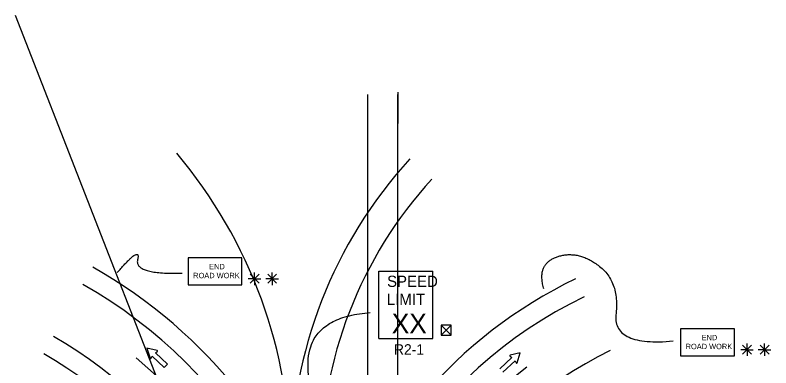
# Model space of a CAD drawing. Extents: x 16604 to 19504, y 6997 to 8305.
# Drawn here: x 16712 to 17319, y 8022 to 8305 of the extents above; entities that cross this region are included whole.
import ezdxf

# ---------------------------------------------------------------- set-up
doc = ezdxf.new("R2010")
doc.units = 0
for name, color, linetype in [('ALI_LEGAL_EX', 7, 'Continuous'), ('MT_SCRATCH_LEVEL_E', 7, 'Continuous'), ('PAVT_EDGE_EX', 7, 'Continuous'), ('TRAFFIC_SIGNS_PR', 7, 'Continuous'), ('TYPICAL_TEXT_DIMEN_PR', 7, 'Continuous')]:
    doc.layers.add(name, color=color, linetype=linetype)

msp = doc.modelspace()

# ---------------------------------------------------------------- linework, layer by layer
at = {"layer": 'ALI_LEGAL_EX'}
for p, q in [((16712.44, 8305.01), (16934.47, 7736.64)), ((16995.53, 8241.3), (16995.53, 7423.16)), ((17019.53, 8241.3), (17019.53, 7423.16))]:
    msp.add_line(p, q, dxfattribs=at)
for points in [[(17019.95, 8218.16), (17019.95, 8243.16)], [(16828.4, 8013.47), (16809.73, 8030.1)], [(17103.8, 8007.23), (17123.26, 8022.93)]]:
    msp.add_lwpolyline(points, dxfattribs=at)
for centre, radius, start, end in [((16545.79, 7943.78), 388, 0, 40.19078), ((17297.79, 7943.78), 364, 137.51601, 180), ((17297.79, 7943.78), 340, 137.51601, 180)]:
    msp.add_arc(centre, radius, start, end, dxfattribs=at)
at = {"layer": 'MT_SCRATCH_LEVEL_E'}
for p, q in [((16826.46, 8035.9), (16818.35, 8037.87)), ((16818.35, 8037.87), (16820.78, 8029.9)), ((16821.6, 8029.78), (16822.6, 8031.29)), ((16822.6, 8031.29), (16832.22, 8022.17)), ((16825.17, 8034.01), (16826.62, 8035.08)), ((16834.8, 8024.89), (16825.17, 8034.01)), ((17111.32, 8030.27), (17101.65, 8021.2)), ((17109.87, 8031.35), (17111.32, 8030.27)), ((17118.14, 8034.12), (17110.04, 8032.16)), ((17115.69, 8026.14), (17118.14, 8034.12)), ((16832.22, 8022.17), (16834.8, 8024.89)), ((17104.21, 8018.47), (17113.88, 8027.53)), ((17113.88, 8027.53), (17114.86, 8026.02))]:
    msp.add_line(p, q, dxfattribs=at)
for centre, start, end in [((16826.34, 8035.45), 306.59404, 76.33096), ((16821.22, 8030.04), 196.98269, 326.52165), ((17110.16, 8031.71), 103.58205, 233.12102), ((17115.25, 8026.29), 213.1934, 342.93033)]:
    msp.add_arc(centre, 0.463, start, end, dxfattribs=at)
at = {"layer": 'PAVT_EDGE_EX'}
for centre, radius, start, end in [((16575.73, 7751.28), 404, 15.917, 60.4732), ((17327.73, 7751.28), 380, 115.76575, 163.04831), ((16575.73, 7751.28), 388, 0, 60.4732), ((17327.73, 7751.28), 364, 115.76575, 180), ((16575.73, 7751.28), 340, 0, 60.4732), ((17327.73, 7751.28), 316, 115.76575, 180), ((16575.73, 7751.28), 324, 0, 60.4732)]:
    msp.add_arc(centre, radius, start, end, dxfattribs=at)
at = {"layer": 'TRAFFIC_SIGNS_PR'}
for p, q in [((17004.62, 8099.47), (17047.82, 8099.47)), ((17004.62, 8045.47), (17004.62, 8099.47)), ((17047.82, 8045.47), (17047.82, 8099.47)), ((17004.62, 8045.47), (17047.82, 8045.47))]:
    msp.add_line(p, q, dxfattribs=at)
for points in [[(16851.38, 8088.59), (16894.58, 8088.59), (16894.58, 8110.19), (16851.38, 8110.19)], [(17246.83, 8031.65), (17290.03, 8031.65), (17290.03, 8053.25), (17246.83, 8053.25)]]:
    msp.add_lwpolyline(points, close=True, dxfattribs=at)
at = {"layer": 'TYPICAL_TEXT_DIMEN_PR'}
for p, q in [((16901.14, 8097.1), (16908.31, 8089.93)), ((16908.31, 8097.1), (16901.14, 8089.93)), ((16904.73, 8093.51), (16904.73, 8098.53)), ((16922.44, 8097.1), (16915.26, 8089.93)), ((16915.27, 8097.1), (16922.44, 8089.93)), ((16918.85, 8093.51), (16918.85, 8098.53)), ((16904.73, 8093.51), (16899.63, 8093.51)), ((16904.73, 8093.51), (16908.31, 8093.51)), ((16904.73, 8093.51), (16909.76, 8093.51)), ((16904.73, 8093.51), (16904.73, 8088.45)), ((16918.85, 8093.51), (16913.75, 8093.51)), ((16918.85, 8093.51), (16922.44, 8093.51)), ((16918.85, 8093.51), (16923.89, 8093.51)), ((16918.85, 8093.51), (16918.85, 8088.45)), ((17054.49, 8056.35), (17062.49, 8048.35)), ((17054.49, 8048.35), (17062.49, 8056.35)), ((17300.17, 8036.57), (17300.17, 8041.58)), ((17314.3, 8036.57), (17314.3, 8041.58)), ((17300.17, 8036.57), (17295.08, 8036.57)), ((17296.59, 8040.15), (17303.76, 8032.98)), ((17303.76, 8040.15), (17296.59, 8032.98)), ((17300.17, 8036.57), (17303.76, 8036.57)), ((17300.17, 8036.57), (17305.21, 8036.57)), ((17300.17, 8036.57), (17300.17, 8031.51)), ((17314.3, 8036.57), (17309.2, 8036.57)), ((17317.89, 8040.15), (17310.71, 8032.98)), ((17310.72, 8040.15), (17317.89, 8032.98)), ((17314.3, 8036.57), (17317.89, 8036.57)), ((17314.3, 8036.57), (17319.34, 8036.57)), ((17314.3, 8036.57), (17314.3, 8031.51))]:
    msp.add_line(p, q, dxfattribs=at)
msp.add_lwpolyline([(17054.49, 8056.35), (17054.49, 8048.35), (17062.49, 8048.35), (17062.49, 8056.35)], close=True, dxfattribs=at)
for points in [[(16794.5, 8098.38), (16813.71, 8120.98), (16807.86, 8096.7), (16846.56, 8098.1)], [(17137.08, 8085.28), (17131.07, 8105.28), (17164, 8116.81), (17197.85, 8091.44), (17192.05, 8039.02), (17240.86, 8043.55)], [(16954.55, 7912.33), (16985.92, 7921.76), (17000.86, 7981.24), (16947.66, 7986.96), (16947.76, 8062.72), (16997.69, 8066.32)]]:
    msp.add_open_spline(points, degree=2, dxfattribs=at)

# ---------------------------------------------------------------- texts
at = {"layer": 'TRAFFIC_SIGNS_PR'}
for s, height, p in [('END', 4.31, (16868.25, 8101.11)), ('ROAD WORK', 4.31, (16855.44, 8093.93)), ('SPEED', 9, (17011.11, 8086.94)), ('LIMIT', 9, (17010.92, 8072.54)), ('XX', 15.785, (17014.87, 8049.7)), ('END', 4.31, (17263.7, 8044.17)), ('ROAD WORK', 4.31, (17250.89, 8036.99)), ('R2-1', 8.37, (17016.63, 8032.6))]:
    msp.add_text(s, height=height, dxfattribs=at).set_placement(p)

doc.saveas('drawing.dxf')
